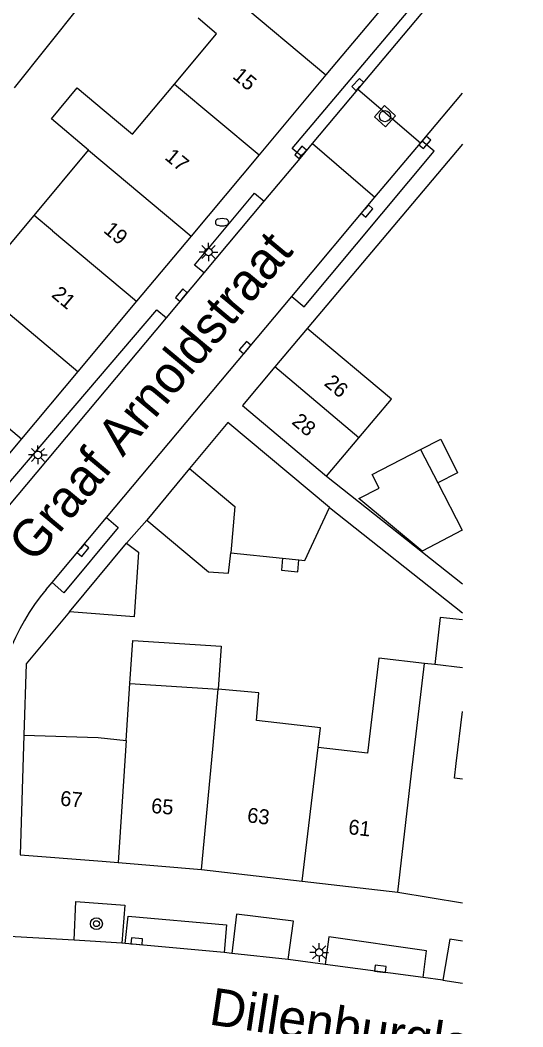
# Model space of a CAD drawing. Extents: x 132573 to 132944, y 398226 to 398676.
# Drawn here: x 132910.4 to 132944.2, y 398274.2 to 398341.8 of the extents above; entities that cross this region are included whole.
import ezdxf

# ---------------------------------------------------------------- set-up
doc = ezdxf.new("R2010")
doc.units = 0
for name, color, linetype in [('gg-afsc-erfafscheiding', 7, 'Continuous'), ('gg-afsc-muur', 7, 'Continuous'), ('gg-anno-huisnummerreeks BGT', 7, 'Continuous'), ('gg-anno-openbare ruimte label', 7, 'Continuous'), ('gg-bbg-bijgebouw', 7, 'Continuous'), ('gg-bbg-gedigitaliseerde bebouwing', 7, 'Continuous'), ('gg-bbg-gedigitaliseerde bijgebouw', 7, 'Continuous'), ('gg-bbg-hoofdgebouw', 7, 'Continuous'), ('gg-bbg-luifel en loopbrug', 7, 'Continuous'), ('gg-bbg-tussenscheiding', 7, 'Continuous'), ('gg-knt-verharding', 7, 'Continuous'), ('gg-knt-verharding nz', 7, 'Continuous'), ('gt-symb-boom', 7, 'Continuous'), ('gt-symb-brandkraan', 7, 'Continuous'), ('gt-symb-kolk', 7, 'Continuous'), ('gt-symb-lichtmast', 7, 'Continuous'), ('gt-symb-rioolschacht', 7, 'Continuous')]:
    doc.layers.add(name, color=color, linetype=linetype)

msp = doc.modelspace()

# ---------------------------------------------------------------- linework, layer by layer
at = {"layer": 'gg-afsc-erfafscheiding'}
for p, q in [((132940.113, 398333.505), (132929.68, 398321.13)), ((132930.994, 398311.203), (132940.113, 398303.978)), ((132931.187, 398309.102), (132940.113, 398302.03))]:
    msp.add_line(p, q, dxfattribs=at)
at = {"layer": 'gg-afsc-muur'}
msp.add_lwpolyline([(132913.72, 398302.11), (132910.8, 398298.62), (132910.64, 398293.82)], dxfattribs=at)
at = {"layer": 'gg-bbg-bijgebouw'}
for p, q in [((132929.68, 398321.13), (132927.505, 398318.54)), ((132927.505, 398318.54), (132925.33, 398315.95)), ((132924.35, 398314.8), (132921.782, 398311.718)), ((132921.782, 398311.718), (132918.9, 398308.26)), ((132913.72, 398302.11), (132917.55, 398306.71))]:
    msp.add_line(p, q, dxfattribs=at)
msp.add_lwpolyline([(132917.55, 398306.71), (132918.34, 398306.11), (132918.058, 398301.771), (132913.72, 398302.11)], dxfattribs=at)
at = {"layer": 'gg-bbg-gedigitaliseerde bebouwing'}
for p, q in [((132911.337, 398328.711), (132914.991, 398333.104)), ((132909.405, 398326.405), (132911.337, 398328.711)), ((132938.261, 398298.56), (132937.562, 398298.642)), ((132940.113, 398298.344), (132938.261, 398298.56)), ((132917.519, 398293.471), (132917.768, 398297.298)), ((132917.768, 398297.298), (132923.708, 398296.912)), ((132939.705, 398291.907), (132940.113, 398295.407))]:
    msp.add_line(p, q, dxfattribs=at)
for points in [[(132920.77, 398337.534), (132923.599, 398340.908), (132922.348, 398341.957)], [(132916.728, 398335.177), (132917.941, 398334.16), (132920.77, 398337.534)], [(132914.991, 398333.104), (132912.492, 398335.198), (132914.229, 398337.271), (132916.728, 398335.177)], [(132937.562, 398298.642), (132934.493, 398299), (132933.748, 398292.603), (132930.427, 398292.992)], [(132930.427, 398292.992), (132930.581, 398294.308), (132926.286, 398294.809), (132926.435, 398296.657), (132923.708, 398296.912)], [(132910.64, 398293.82), (132915.64, 398293.66), (132917.519, 398293.471)], [(132940.113, 398290.862), (132939.592, 398290.939), (132939.705, 398291.907)]]:
    msp.add_lwpolyline(points, dxfattribs=at)
at = {"layer": 'gg-bbg-gedigitaliseerde bijgebouw'}
for p, q in [((132910.008, 398337.28), (132914.457, 398342.827)), ((132925.33, 398315.95), (132930.994, 398311.203)), ((132931.187, 398309.102), (132924.35, 398314.8)), ((132930.994, 398311.203), (132933.165, 398313.787)), ((132937.301, 398313.007), (132938.462, 398310.761)), ((132924.542, 398306.051), (132928.031, 398305.699)), ((132928.031, 398305.699), (132929.133, 398305.588))]:
    msp.add_line(p, q, dxfattribs=at)
for points in [[(132933.165, 398313.787), (132935.345, 398316.382), (132929.68, 398321.13)], [(132933.154, 398309.701), (132934.524, 398310.41), (132934.05, 398311.326), (132937.301, 398313.007)], [(132938.462, 398310.761), (132940.109, 398307.575), (132937.405, 398306.177), (132933.154, 398309.701)], [(132929.133, 398305.588), (132929.517, 398305.549), (132931.187, 398309.102)], [(132918.9, 398308.26), (132923.054, 398304.778), (132924.394, 398304.692), (132924.542, 398306.051)]]:
    msp.add_lwpolyline(points, dxfattribs=at)
at = {"layer": 'gg-bbg-hoofdgebouw'}
for p, q in [((132934.77, 398342.704), (132930.949, 398338.146)), ((132930.949, 398338.146), (132926.448, 398332.774)), ((132926.448, 398332.774), (132921.883, 398327.328)), ((132921.883, 398327.328), (132918.214, 398322.95)), ((132918.214, 398322.95), (132914.27, 398318.244)), ((132914.27, 398318.244), (132910.483, 398313.725)), ((132910.483, 398313.725), (132906.562, 398309.046)), ((132910.64, 398293.82), (132910.391, 398285.793)), ((132916.986, 398285.266), (132922.578, 398284.807)), ((132922.578, 398284.807), (132929.357, 398284.017)), ((132929.357, 398284.017), (132935.77, 398283.27)), ((132935.77, 398283.27), (132940.113, 398282.563))]:
    msp.add_line(p, q, dxfattribs=at)
msp.add_lwpolyline([(132910.391, 398285.793), (132915.906, 398285.351), (132916.986, 398285.266)], dxfattribs=at)
at = {"layer": 'gg-bbg-luifel en loopbrug'}
for points in [[(132937.301, 398313.007), (132938.671, 398313.686), (132939.793, 398311.421), (132938.462, 398310.761)], [(132928.031, 398305.699), (132927.951, 398304.893), (132929.051, 398304.782), (132929.133, 398305.588)], [(132940.113, 398301.552), (132938.63, 398301.725), (132938.261, 398298.56)], [(132917.768, 398297.298), (132917.955, 398300.181), (132923.895, 398299.795), (132923.708, 398296.912)]]:
    msp.add_lwpolyline(points, dxfattribs=at)
at = {"layer": 'gg-bbg-tussenscheiding'}
for p, q in [((132924.022, 398343.954), (132930.949, 398338.146)), ((132920.77, 398337.534), (132926.448, 398332.774)), ((132914.991, 398333.104), (132921.883, 398327.328)), ((132912.562, 398327.685), (132911.337, 398328.711)), ((132912.562, 398327.685), (132918.214, 398322.95)), ((132908.23, 398323.307), (132914.27, 398318.244)), ((132902.912, 398320.07), (132910.483, 398313.725)), ((132933.165, 398313.787), (132927.505, 398318.54)), ((132936.703, 398291.276), (132937.562, 398298.642)), ((132917.519, 398293.471), (132916.986, 398285.266)), ((132929.357, 398284.017), (132930.427, 398292.992)), ((132935.77, 398283.27), (132936.703, 398291.276))]:
    msp.add_line(p, q, dxfattribs=at)
for points in [[(132921.782, 398311.718), (132924.825, 398309.182), (132924.542, 398306.051)], [(132922.578, 398284.807), (132923.332, 398292.887), (132923.708, 398296.912)]]:
    msp.add_lwpolyline(points, dxfattribs=at)
at = {"layer": 'gg-knt-verharding'}
for p, q in [((132933.079, 398337.157), (132940.113, 398345.536)), ((132930.046, 398333.544), (132933.079, 398337.157)), ((132937.299, 398333.575), (132933.079, 398337.157)), ((132937.406, 398333.703), (132940.113, 398336.929)), ((132929.318, 398332.677), (132930.046, 398333.544)), ((132930.046, 398333.544), (132934.241, 398329.93)), ((132934.241, 398329.93), (132937.299, 398333.575)), ((132937.299, 398333.575), (132937.406, 398333.703)), ((132926.789, 398329.665), (132929.318, 398332.677)), ((132922.751, 398324.854), (132926.789, 398329.665)), ((132928.65, 398323.266), (132934.241, 398329.93)), ((132920.22, 398321.839), (132922.751, 398324.854)), ((132916.199, 398308.426), (132928.65, 398323.266)), ((132906.52, 398305.52), (132920.22, 398321.839)), ((132912.552, 398304.08), (132916.199, 398308.426)), ((132917.55, 398306.71), (132918.9, 398308.26)), ((132912.151, 398303.602), (132912.552, 398304.08)), ((132914.016, 398280.052), (132908.181, 398280.39)), ((132917.229, 398279.847), (132914.016, 398280.052)), ((132917.46, 398279.832), (132917.229, 398279.847)), ((132924.108, 398279.221), (132917.46, 398279.832)), ((132924.626, 398279.171), (132924.108, 398279.221)), ((132928.413, 398278.766), (132924.626, 398279.171)), ((132930.89, 398278.434), (132928.413, 398278.766)), ((132937.471, 398277.551), (132930.89, 398278.434)), ((132938.801, 398277.373), (132937.471, 398277.551)), ((132938.801, 398277.373), (132940.113, 398277.176))]:
    msp.add_line(p, q, dxfattribs=at)
for points in [[(132914.016, 398280.052), (132914.134, 398282.647), (132917.436, 398282.399), (132917.229, 398279.847)], [(132917.46, 398279.832), (132917.649, 398281.679), (132924.262, 398281.088), (132924.108, 398279.221)], [(132928.413, 398278.766), (132928.775, 398281.341), (132924.938, 398281.796), (132924.626, 398279.171)], [(132937.471, 398277.551), (132937.703, 398279.348), (132931.15, 398280.284), (132930.89, 398278.434)], [(132940.113, 398279.981), (132939.267, 398280.124), (132938.801, 398277.373)]]:
    msp.add_lwpolyline(points, dxfattribs=at)
msp.add_arc((132923.867, 398293.772), 15.294, 140.00224, 178.31374, dxfattribs=at)
at = {"layer": 'gg-knt-verharding nz'}
for points in [[(132929.318, 398332.677), (132928.683, 398333.209), (132940.113, 398346.771)], [(132928.65, 398323.266), (132929.477, 398322.572), (132938.218, 398333.021), (132937.406, 398333.703)], [(132922.751, 398324.854), (132922.119, 398325.384), (132926.15, 398330.201), (132926.789, 398329.665)], [(132907.015, 398307.688), (132919.585, 398322.372), (132920.22, 398321.839)], [(132916.199, 398308.426), (132916.986, 398307.765), (132913.33, 398303.371), (132912.552, 398304.08)]]:
    msp.add_lwpolyline(points, dxfattribs=at)
at = {"layer": 'gt-symb-boom'}
for radius in [0.4, 0.2]:
    msp.add_circle((132915.519, 398281.164), radius, dxfattribs=at)
at = {"layer": 'gt-symb-brandkraan'}
for centre, radius, start, end in [((132923.721, 398328.256), 0.206, 107.56694, 252.43307), ((132924.564, 398325.592), 3, 106.89205, 107.56694), ((132924.564, 398330.92), 3, 252.43307, 253.10797), ((132923.965, 398327.565), 0.938, 73.10799, 106.89205), ((132923.965, 398328.947), 0.938, 253.10797, 286.89206), ((132923.366, 398325.592), 3, 72.43309, 73.10799), ((132923.366, 398330.92), 3, 286.89206, 287.56695), ((132924.209, 398328.256), 0.206, 287.56695, 72.43309)]:
    msp.add_arc(centre, radius, start, end, dxfattribs=at)
at = {"layer": 'gt-symb-kolk'}
for points in [[(132933.232, 398337.364), (132933.486, 398337.64), (132933.191, 398337.911), (132932.684, 398337.359), (132932.978, 398337.088), (132933.232, 398337.364)], [(132937.442, 398333.745), (132937.2, 398333.459), (132937.505, 398333.2), (132937.99, 398333.773), (132937.684, 398334.031), (132937.442, 398333.745)], [(132929.395, 398332.815), (132929.637, 398333.102), (132929.331, 398333.36), (132928.847, 398332.786), (132929.153, 398332.528), (132929.395, 398332.815)], [(132933.56, 398329.139), (132933.316, 398328.854), (132933.62, 398328.594), (132934.108, 398329.164), (132933.804, 398329.424), (132933.56, 398329.139)], [(132921.382, 398323.23), (132921.623, 398323.518), (132921.316, 398323.774), (132920.835, 398323.199), (132921.141, 398322.942), (132921.382, 398323.23)], [(132925.663, 398319.711), (132925.905, 398319.998), (132925.599, 398320.256), (132925.115, 398319.682), (132925.421, 398319.424), (132925.663, 398319.711)], [(132914.465, 398306.36), (132914.224, 398306.073), (132914.53, 398305.816), (132915.012, 398306.39), (132914.706, 398306.647), (132914.465, 398306.36)], [(132918.212, 398279.784), (132918.585, 398279.748), (132918.623, 398280.147), (132917.877, 398280.218), (132917.839, 398279.82), (132918.212, 398279.784)], [(132934.571, 398277.94), (132934.943, 398277.894), (132934.992, 398278.291), (132934.248, 398278.383), (132934.199, 398277.986), (132934.571, 398277.94)]]:
    msp.add_lwpolyline(points, dxfattribs=at)
at = {"layer": 'gt-symb-lichtmast'}
for p, q in [((132922.873, 398326.434), (132922.608, 398326.699)), ((132923.05, 398326.507), (132923.05, 398326.882)), ((132923.227, 398326.434), (132923.492, 398326.699)), ((132922.8, 398326.257), (132922.425, 398326.257)), ((132922.873, 398326.08), (132922.608, 398325.815)), ((132923.492, 398325.815), (132923.227, 398326.08)), ((132923.3, 398326.257), (132923.675, 398326.257)), ((132923.05, 398326.007), (132923.05, 398325.632)), ((132911.588, 398312.882), (132911.588, 398313.257)), ((132911.338, 398312.632), (132910.963, 398312.632)), ((132911.411, 398312.809), (132911.146, 398313.074)), ((132911.765, 398312.809), (132912.03, 398313.074)), ((132911.838, 398312.632), (132912.213, 398312.632)), ((132911.411, 398312.455), (132911.146, 398312.19)), ((132911.588, 398312.382), (132911.588, 398312.007)), ((132912.03, 398312.19), (132911.765, 398312.455)), ((132930.31, 398279.414), (132930.045, 398279.679)), ((132930.487, 398279.487), (132930.487, 398279.862)), ((132930.664, 398279.414), (132930.929, 398279.679)), ((132930.237, 398279.237), (132929.862, 398279.237)), ((132930.31, 398279.06), (132930.045, 398278.795)), ((132930.487, 398278.987), (132930.487, 398278.612)), ((132930.929, 398278.795), (132930.664, 398279.06)), ((132930.737, 398279.237), (132931.112, 398279.237))]:
    msp.add_line(p, q, dxfattribs=at)
for centre in [(132923.05, 398326.257), (132911.588, 398312.632), (132930.487, 398279.237)]:
    msp.add_circle(centre, 0.25, dxfattribs=at)
at = {"layer": 'gt-symb-rioolschacht'}
msp.add_lwpolyline([(132934.943, 398334.67), (132935.616, 398335.409), (132934.877, 398336.082), (132934.204, 398335.343)], close=True, dxfattribs=at)
msp.add_circle((132934.91, 398335.376), 0.375, dxfattribs=at)

# ---------------------------------------------------------------- texts
at = {"layer": 'gg-anno-huisnummerreeks BGT'}
for s, rotation, p in [('15', 320.1, (132924.609, 398337.973)), ('17', 320.1, (132920.053, 398332.531)), ('19', 320.1, (132915.938, 398327.623)), ('21', 320.1, (132912.439, 398323.296)), ('26', 320, (132930.763, 398317.359)), ('28', 320, (132928.588, 398314.769)), ('67', 355.4, (132913.059, 398289.091)), ('65', 355.3, (132919.17, 398288.599)), ('63', 353.3, (132925.615, 398287.977)), ('61', 353.3, (132932.413, 398287.185))]:
    msp.add_text(s, height=1, rotation=rotation, dxfattribs=at).set_placement(p)
at = {"layer": 'gg-anno-openbare ruimte label'}
for s, rotation, p in [('Graaf Arnoldstraat', 50.2, (132911.342, 398305.3)), ('Dillenburglaan', 351.4, (132923.02, 398274.411))]:
    msp.add_text(s, height=2.5, rotation=rotation, dxfattribs=at).set_placement(p)

doc.saveas('drawing.dxf')
